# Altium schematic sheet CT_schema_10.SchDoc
size 391 x 278 mm
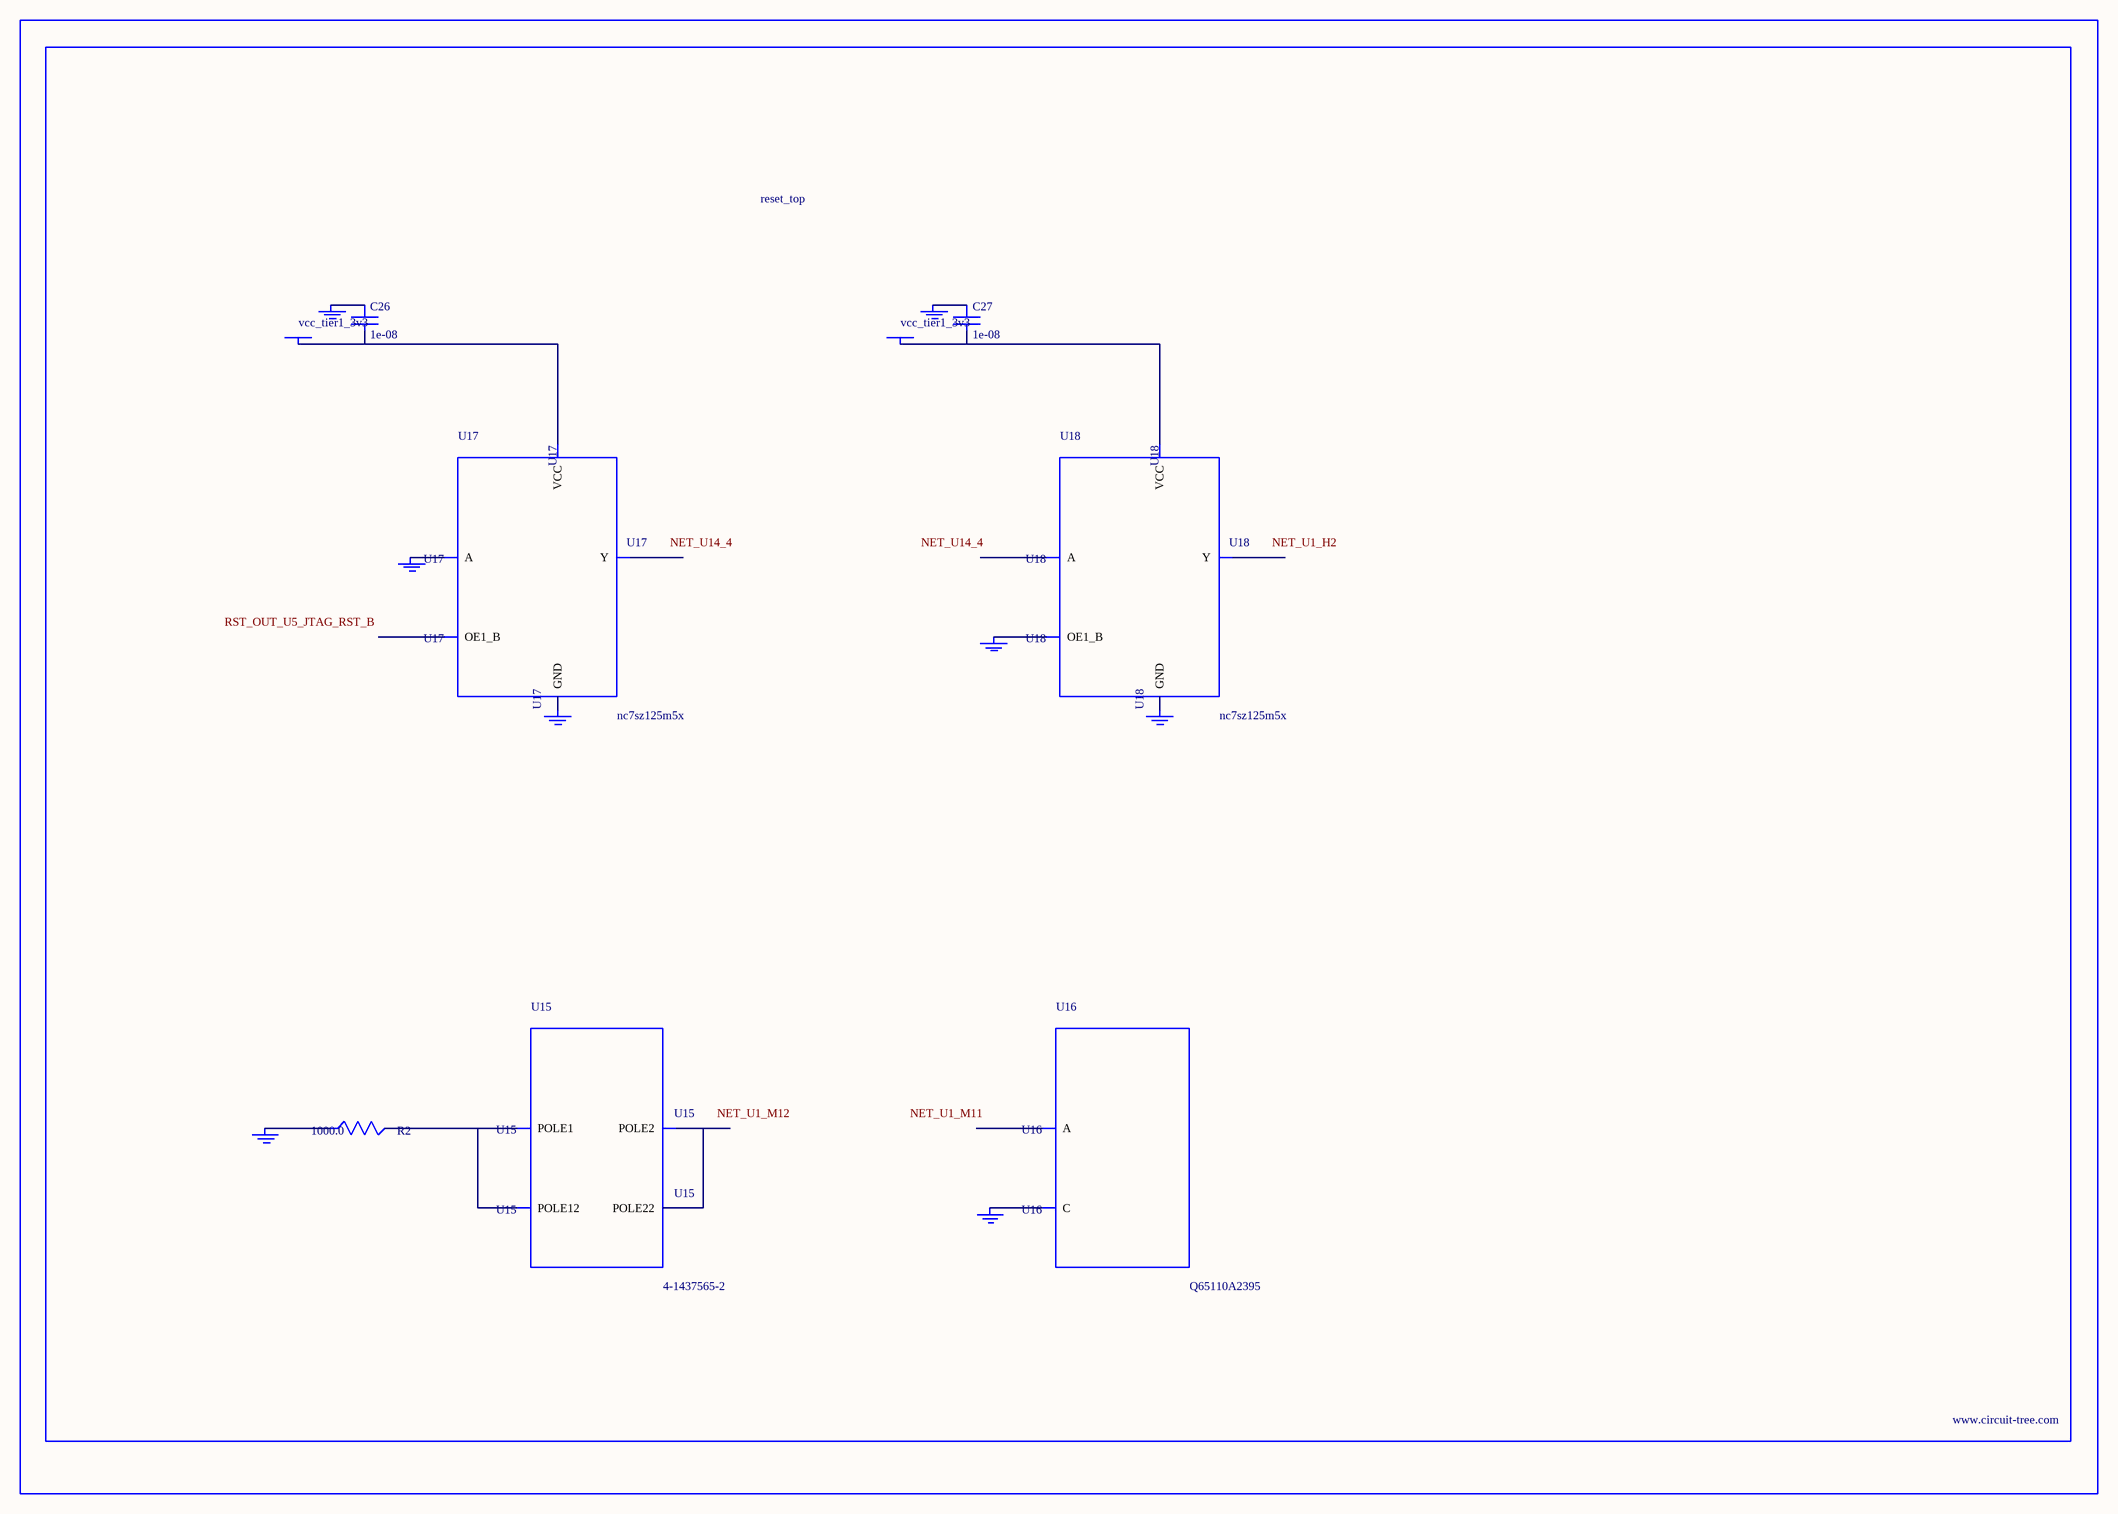
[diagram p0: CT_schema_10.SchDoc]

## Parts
BORDER9  (no value)
C26  1e-08  [C0402]
C27  1e-08  [C0402]
GND_INSTANCE_9_0  (no value)
GND_INSTANCE_9_1  (no value)
GND_INSTANCE_9_2  (no value)
GND_INSTANCE_9_3  (no value)
GND_INSTANCE_9_4  (no value)
GND_INSTANCE_9_5  (no value)
GND_INSTANCE_9_6  (no value)
GND_INSTANCE_9_7  (no value)
POWER_INSTANCE_9_0  vcc_tier1_3v3
POWER_INSTANCE_9_1  vcc_tier1_3v3
R2  1000.0  [R0603]
U15  4-1437565-2  [SW_4-1437565-2]
U16  Q65110A2395  [LGM67K-G1J2-24-Z]
U17  nc7sz125m5x  [NC7SZ125M5X]
U18  nc7sz125m5x  [NC7SZ125M5X]

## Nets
NetC26_1: C26.1 GND_INSTANCE_9_2.0(GND)
NetC26_2: C26.2 POWER_INSTANCE_9_0.0(PWR) U17.5(VCC)
NetC27_1: C27.1 GND_INSTANCE_9_5.0(GND)
NetC27_2: C27.2 POWER_INSTANCE_9_1.0(PWR) U18.5(VCC)
NetGND_INSTANCE_9_0_0: GND_INSTANCE_9_0.0(GND) R2.1
NetGND_INSTANCE_9_1_0: GND_INSTANCE_9_1.0(GND) U16.C
NetGND_INSTANCE_9_3_0: GND_INSTANCE_9_3.0(GND) U17.2(A)
NetGND_INSTANCE_9_4_0: GND_INSTANCE_9_4.0(GND) U17.3(GND)
NetGND_INSTANCE_9_6_0: GND_INSTANCE_9_6.0(GND) U18.1(OE1_B)
NetGND_INSTANCE_9_7_0: GND_INSTANCE_9_7.0(GND) U18.3(GND)
NetR2_2: R2.2 U15.1(POLE1) U15.2(POLE12)
NetU15_3: U15.3(POLE2) U15.4(POLE22)

Not connected (* = marked no-connect by the designer): U16 A; U17 1(OE1_B) 4(Y); U18 2(A) 4(Y)

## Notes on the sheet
- Labels drawn without touching a wire or pin: NET_U1_H2, NET_U1_M11, NET_U1_M12, NET_U14_4, RST_OUT_U5_JTAG_RST_B

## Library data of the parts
BORDER9 = BORDER_PAGE9
C26 C27 = C0402C103K3RAC
GND_INSTANCE_9_0-GND_INSTANCE_9_7 = GND
POWER_INSTANCE_9_0 POWER_INSTANCE_9_1 = PWR
R2 = RC0603JR-071KL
